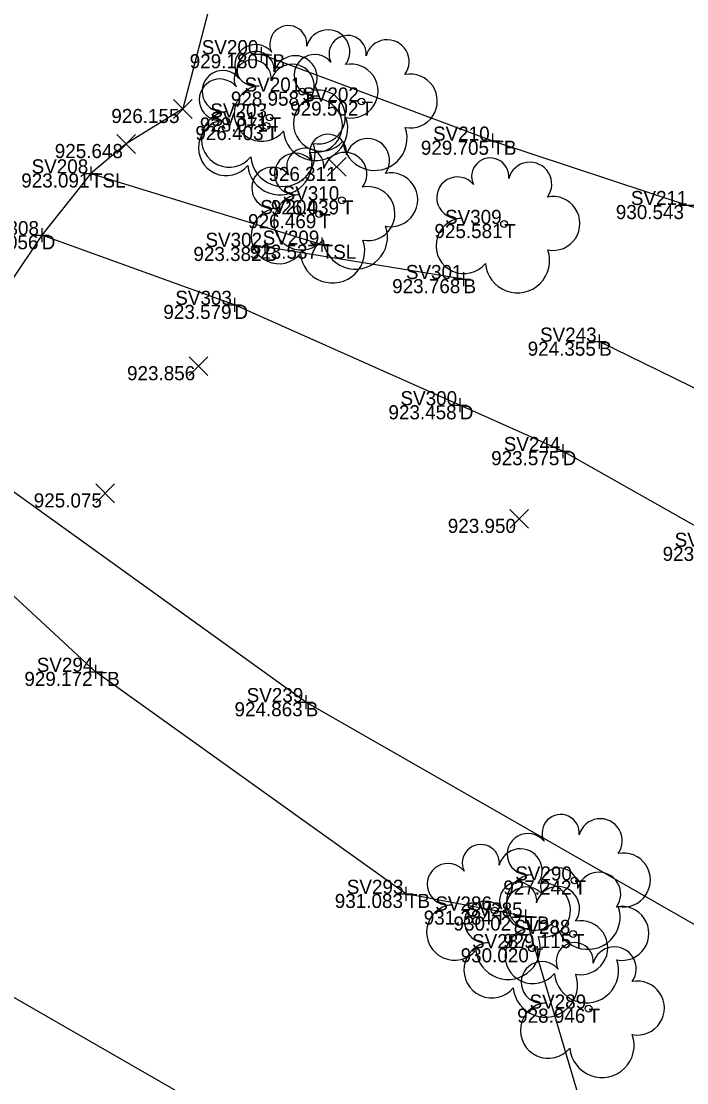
# Model space of a CAD drawing. Extents: x 1988835 to 1989144, y 657973 to 659339.
# Drawn here: x 1988889.6 to 1988936.8, y 658662.1 to 658737.4 of the extents above; entities that cross this region are included whole.
import ezdxf

# ---------------------------------------------------------------- set-up
doc = ezdxf.new("R2010")
doc.units = 0
for name, color, linetype in [('DR_X_Ditch', 7, 'Continuous'), ('DT_X_Terrain_Boundary', 7, 'Continuous'), ('SV_X_Break_Lines', 7, 'Continuous'), ('SV_X_Random_Point', 7, 'Continuous'), ('SV_X_Shot_Marker', 7, 'Continuous'), ('SV_X_Text_Comment', 7, 'Continuous'), ('SV_X_Toe_of_Slope', 7, 'Continuous'), ('SV_X_Top_of_Bank', 7, 'Continuous'), ('UT_X_Telecom', 7, 'Continuous'), ('UT_X_Telecom_Cells', 7, 'Continuous'), ('VG_X_Cells', 7, 'Continuous')]:
    doc.layers.add(name, color=color, linetype=linetype)

msp = doc.modelspace()

# ---------------------------------------------------------------- linework, layer by layer
at = {"layer": 'DR_X_Ditch'}
for points in [[(1988920.687, 658710.159), (1988904.704, 658717.281), (1988891.031, 658722.224)], [(1988954.33, 658694.137), (1988940.011, 658700.115), (1988927.983, 658706.906), (1988920.687, 658710.159)]]:
    msp.add_lwpolyline(points, dxfattribs=at)
at = {"layer": 'DT_X_Terrain_Boundary'}
msp.add_lwpolyline([(1988987.829, 658845.226), (1988984.806, 658799.592), (1988977.838, 658799.782), (1988968.827, 658798.912), (1988942.792, 658792.822), (1988927.355, 658779.107), (1988913.541, 658771.147), (1988908.127, 658758.455), (1988901.041, 658731.181), (1988897.019, 658728.695), (1988894.525, 658726.606), (1988891.031, 658722.224), (1988888.806, 658718.864), (1988886.026, 658711.785), (1988888.695, 658704.246), (1988881.579, 658703.527), (1988864.624, 658687.792), (1988839.989, 658661.752), (1988877.263, 658674.92), (1988925.042, 658647.449), (1988928.997, 658641.521), (1988939.918, 658638.356), (1988953.745, 658630.003), (1988967.235, 658593.527)], dxfattribs=at)
at = {"layer": 'SV_X_Break_Lines'}
for points in [[(1988920.949, 658719.109), (1988906.849, 658721.392)], [(1988961.012, 658699.789), (1988959.296, 658702.449), (1988957.403, 658701.554), (1988930.572, 658714.671)], [(1988950.438, 658683.541), (1988950.966, 658681.818), (1988947.272, 658678.12), (1988941.777, 658670.765), (1988909.757, 658689.092), (1988888.695, 658704.246)]]:
    msp.add_lwpolyline(points, dxfattribs=at)
at = {"layer": 'SV_X_Random_Point'}
for p, q in [((1988900.374, 658730.514), (1988901.708, 658731.849)), ((1988900.374, 658731.849), (1988901.708, 658730.514)), ((1988896.352, 658728.027), (1988897.685, 658729.362)), ((1988896.352, 658729.362), (1988897.685, 658728.027)), ((1988911.284, 658726.402), (1988912.618, 658727.737)), ((1988911.284, 658727.737), (1988912.618, 658726.402)), ((1988901.482, 658712.265), (1988902.815, 658713.6)), ((1988901.482, 658713.6), (1988902.815, 658712.265)), ((1988894.872, 658703.239), (1988896.206, 658704.574)), ((1988894.872, 658704.574), (1988896.206, 658703.239)), ((1988924.229, 658701.434), (1988925.563, 658702.769)), ((1988924.229, 658702.769), (1988925.563, 658701.434))]:
    msp.add_line(p, q, dxfattribs=at)
at = {"layer": 'SV_X_Shot_Marker'}
for p, q in [((1988906.592, 658735.565), (1988906.592, 658734.565)), ((1988906.092, 658735.065), (1988907.092, 658735.065)), ((1988906.592, 658735.065), (1988906.592, 658735.065)), ((1988922.496, 658728.928), (1988923.496, 658728.928)), ((1988922.996, 658729.428), (1988922.996, 658728.428)), ((1988922.996, 658728.928), (1988922.996, 658728.928)), ((1988894.025, 658726.606), (1988895.025, 658726.606)), ((1988894.525, 658727.106), (1988894.525, 658726.106)), ((1988894.525, 658726.606), (1988894.525, 658726.606)), ((1988936.302, 658724.364), (1988937.302, 658724.364)), ((1988891.031, 658722.724), (1988891.031, 658721.724)), ((1988890.531, 658722.224), (1988891.531, 658722.224)), ((1988891.031, 658722.224), (1988891.031, 658722.224)), ((1988910.893, 658722.052), (1988910.893, 658721.052)), ((1988906.349, 658721.392), (1988907.349, 658721.392)), ((1988906.849, 658721.892), (1988906.849, 658720.892)), ((1988906.849, 658721.392), (1988906.849, 658721.392)), ((1988910.393, 658721.552), (1988911.393, 658721.552)), ((1988910.893, 658721.552), (1988910.893, 658721.552)), ((1988920.449, 658719.109), (1988921.449, 658719.109)), ((1988920.949, 658719.609), (1988920.949, 658718.609)), ((1988920.949, 658719.109), (1988920.949, 658719.109)), ((1988904.704, 658717.781), (1988904.704, 658716.781)), ((1988904.204, 658717.281), (1988905.204, 658717.281)), ((1988904.704, 658717.281), (1988904.704, 658717.281)), ((1988930.572, 658715.171), (1988930.572, 658714.171)), ((1988930.072, 658714.671), (1988931.072, 658714.671)), ((1988930.572, 658714.671), (1988930.572, 658714.671)), ((1988920.687, 658710.659), (1988920.687, 658709.659)), ((1988920.187, 658710.159), (1988921.187, 658710.159)), ((1988920.687, 658710.159), (1988920.687, 658710.159)), ((1988927.483, 658706.906), (1988928.483, 658706.906)), ((1988927.983, 658707.406), (1988927.983, 658706.406)), ((1988927.983, 658706.906), (1988927.983, 658706.906)), ((1988894.359, 658691.243), (1988895.359, 658691.243)), ((1988894.859, 658691.743), (1988894.859, 658690.743)), ((1988894.859, 658691.243), (1988894.859, 658691.243)), ((1988909.757, 658689.592), (1988909.757, 658688.592)), ((1988909.257, 658689.092), (1988910.257, 658689.092)), ((1988909.757, 658689.092), (1988909.757, 658689.092)), ((1988916.868, 658675.991), (1988916.868, 658674.991)), ((1988916.368, 658675.491), (1988917.368, 658675.491)), ((1988916.868, 658675.491), (1988916.868, 658675.491)), ((1988924.845, 658673.887), (1988925.845, 658673.887)), ((1988925.345, 658674.387), (1988925.345, 658673.387)), ((1988925.345, 658673.887), (1988925.345, 658673.887))]:
    msp.add_line(p, q, dxfattribs=at)
at = {"layer": 'SV_X_Toe_of_Slope'}
msp.add_lwpolyline([(1988894.525, 658726.606), (1988910.893, 658721.552)], dxfattribs=at)
at = {"layer": 'SV_X_Top_of_Bank'}
for points in [[(1988906.592, 658735.065), (1988922.996, 658728.928), (1988936.802, 658724.364), (1988946.553, 658721.548), (1988963.916, 658715.502), (1988970.033, 658699.243), (1988969.072, 658687.698)], [(1988925.042, 658647.449), (1988930.237, 658657.354), (1988925.345, 658673.887), (1988916.868, 658675.491), (1988894.859, 658691.243), (1988881.579, 658703.527)]]:
    msp.add_lwpolyline(points, dxfattribs=at)
at = {"layer": 'VG_X_Cells'}
for centre in [(1988909.511, 658732.411), (1988913.715, 658731.708), (1988906.982, 658729.97), (1988907.191, 658730.574), (1988912.327, 658724.699), (1988910.713, 658723.719), (1988923.828, 658723.019), (1988928.827, 658676.442), (1988923.159, 658674.308), (1988928.72, 658672.646), (1988925.807, 658671.633), (1988929.821, 658667.35)]:
    msp.add_circle(centre, 0.24, dxfattribs=at)
for centre, radius, start, end in [((1988908.527, 658735.778), 1.317, 354.0047, 205.97412), ((1988911.337, 658735.24), 1.553, 323.82996, 165.0376), ((1988912.731, 658735.075), 1.317, 354.0047, 205.97412), ((1988906.201, 658734.275), 1.471, 39.06254, 279.54124), ((1988915.541, 658734.537), 1.553, 323.82996, 165.0376), ((1988906.207, 658733.941), 1.317, 354.0047, 205.97412), ((1988909.017, 658733.403), 1.553, 323.82996, 165.0376), ((1988910.406, 658733.572), 1.471, 39.06254, 279.54124), ((1988905.998, 658733.337), 1.317, 354.0047, 205.97412), ((1988908.808, 658732.799), 1.553, 323.82996, 165.0376), ((1988912.971, 658732.447), 1.915, 259.14531, 101.45961), ((1988903.672, 658731.834), 1.471, 39.06254, 279.54124), ((1988903.881, 658732.438), 1.471, 39.06254, 279.54124), ((1988917.175, 658731.744), 1.915, 259.14531, 101.45961), ((1988906.657, 658730.862), 1.974, 96.17219, 320.57371), ((1988910.651, 658730.61), 1.915, 259.14531, 101.45961), ((1988910.862, 658730.159), 1.974, 96.17219, 320.57371), ((1988910.442, 658730.006), 1.915, 259.14531, 101.45961), ((1988904.337, 658729.025), 1.974, 96.17219, 320.57371), ((1988904.128, 658728.421), 1.974, 96.17219, 320.57371), ((1988910.457, 658729.806), 2.284, 184.94757, 19.45715), ((1988914.661, 658729.103), 2.284, 184.94757, 19.45715), ((1988908.137, 658727.968), 2.284, 184.94757, 19.45715), ((1988911.343, 658728.066), 1.317, 354.0047, 205.97412), ((1988914.153, 658727.528), 1.553, 323.82996, 165.0376), ((1988907.928, 658727.364), 2.284, 184.94757, 19.45715), ((1988909.017, 658726.563), 1.471, 39.06254, 279.54124), ((1988909.729, 658727.087), 1.317, 354.0047, 205.97412), ((1988912.539, 658726.548), 1.553, 323.82996, 165.0376), ((1988922.844, 658726.387), 1.317, 354.0047, 205.97412), ((1988925.654, 658725.848), 1.553, 323.82996, 165.0376), ((1988907.404, 658725.583), 1.471, 39.06254, 279.54124), ((1988915.787, 658724.735), 1.915, 259.14531, 101.45961), ((1988914.173, 658723.755), 1.915, 259.14531, 101.45961), ((1988920.519, 658724.883), 1.471, 39.06254, 279.54124), ((1988909.473, 658723.15), 1.974, 96.17219, 320.57371), ((1988927.288, 658723.055), 1.915, 259.14531, 101.45961), ((1988907.86, 658722.171), 1.974, 96.17219, 320.57371), ((1988920.975, 658721.471), 1.974, 96.17219, 320.57371), ((1988913.273, 658722.094), 2.284, 184.94757, 19.45715), ((1988911.659, 658721.114), 2.284, 184.94757, 19.45715), ((1988924.774, 658720.414), 2.284, 184.94757, 19.45715), ((1988927.843, 658679.809), 1.317, 354.0047, 205.97412), ((1988930.653, 658679.271), 1.553, 323.82996, 165.0376), ((1988925.518, 658678.306), 1.471, 39.06254, 279.54124), ((1988922.175, 658677.676), 1.317, 354.0047, 205.97412), ((1988924.985, 658677.137), 1.553, 323.82996, 165.0376), ((1988932.287, 658676.478), 1.915, 259.14531, 101.45961), ((1988919.85, 658676.172), 1.471, 39.06254, 279.54124), ((1988925.974, 658674.893), 1.974, 96.17219, 320.57371), ((1988927.736, 658676.013), 1.317, 354.0047, 205.97412), ((1988930.546, 658675.475), 1.553, 323.82996, 165.0376), ((1988924.823, 658675.001), 1.317, 354.0047, 205.97412), ((1988925.411, 658674.51), 1.471, 39.06254, 279.54124), ((1988927.633, 658674.462), 1.553, 323.82996, 165.0376), ((1988926.619, 658674.344), 1.915, 259.14531, 101.45961), ((1988920.306, 658672.76), 1.974, 96.17219, 320.57371), ((1988922.497, 658673.497), 1.471, 39.06254, 279.54124), ((1988929.773, 658673.837), 2.284, 184.94757, 19.45715), ((1988932.18, 658672.682), 1.915, 259.14531, 101.45961), ((1988925.867, 658671.097), 1.974, 96.17219, 320.57371), ((1988929.267, 658671.669), 1.915, 259.14531, 101.45961), ((1988924.106, 658671.703), 2.284, 184.94757, 19.45715), ((1988922.953, 658670.084), 1.974, 96.17219, 320.57371), ((1988928.837, 658670.717), 1.317, 354.0047, 205.97412), ((1988931.647, 658670.179), 1.553, 323.82996, 165.0376), ((1988929.667, 658670.04), 2.284, 184.94757, 19.45715), ((1988926.511, 658669.214), 1.471, 39.06254, 279.54124), ((1988926.753, 658669.028), 2.284, 184.94757, 19.45715), ((1988933.281, 658667.386), 1.915, 259.14531, 101.45961), ((1988926.967, 658665.801), 1.974, 96.17219, 320.57371), ((1988930.767, 658664.745), 2.284, 184.94757, 19.45715)]:
    msp.add_arc(centre, radius, start, end, dxfattribs=at)

# ---------------------------------------------------------------- texts
at = {"layer": 'SV_X_Text_Comment'}
for s, p in [('SV200', (1988902.385, 658735.065)), ('SV201', (1988905.424, 658732.411)), ('SV202', (1988909.512, 658731.708)), ('SV203', (1988902.995, 658730.574)), ('SV311', (1988902.999, 658729.97)), ('SV210', (1988918.788, 658728.928)), ('SV208', (1988890.319, 658726.606)), ('SV310', (1988908.12, 658724.699)), ('SV211', (1988932.819, 658724.364)), ('SV204', (1988906.535, 658723.719)), ('SV309', (1988919.64, 658723.019)), ('SV308', (1988886.825, 658722.224)), ('SV302', (1988902.646, 658721.392)), ('SV209', (1988906.706, 658721.552)), ('SV301', (1988916.862, 658719.109)), ('SV303', (1988900.508, 658717.281)), ('SV243', (1988926.376, 658714.671)), ('SV300', (1988916.48, 658710.159)), ('SV244', (1988923.805, 658706.906)), ('SV241', (1988935.924, 658700.115)), ('SV294', (1988890.682, 658691.243)), ('SV239', (1988905.57, 658689.092)), ('SV290', (1988924.62, 658676.442)), ('SV293', (1988912.673, 658675.491)), ('SV286', (1988918.949, 658674.308)), ('SV285', (1988921.128, 658673.887)), ('SV288', (1988924.514, 658672.646)), ('SV287', (1988921.558, 658671.633)), ('SV289', (1988925.633, 658667.35))]:
    msp.add_text(s, height=1, dxfattribs=at).set_placement(p)
at = {"layer": 'UT_X_Telecom'}
for s, p in [('TB', (1988906.592, 658734.065)), ('T', (1988909.511, 658731.411)), ('T', (1988913.715, 658730.708)), ('T', (1988907.191, 658729.574)), ('T', (1988906.982, 658728.97)), ('TB', (1988922.996, 658727.928)), ('TSL', (1988894.525, 658725.606)), ('T', (1988912.327, 658723.699)), ('T', (1988910.713, 658722.719)), ('T', (1988923.828, 658722.019)), ('D', (1988891.031, 658721.224)), ('B', (1988906.849, 658720.392)), ('TSL', (1988910.893, 658720.552)), ('B', (1988920.949, 658718.109)), ('D', (1988904.704, 658716.281)), ('B', (1988930.572, 658713.671)), ('D', (1988920.687, 658709.159)), ('D', (1988927.983, 658705.906)), ('TB', (1988894.859, 658690.243)), ('B', (1988909.757, 658688.092)), ('T', (1988928.827, 658675.442)), ('TB', (1988916.868, 658674.491)), ('T', (1988923.159, 658673.308)), ('TB', (1988925.345, 658672.887)), ('T', (1988928.72, 658671.646)), ('T', (1988925.807, 658670.633)), ('T', (1988929.821, 658666.35))]:
    msp.add_text(s, height=1, dxfattribs=at).set_placement(p)
at = {"layer": 'UT_X_Telecom_Cells'}
for s, p in [('929.180', (1988901.531, 658734.065)), ('928.958', (1988904.451, 658731.411)), ('929.502', (1988908.659, 658730.708)), ('926.155', (1988895.97, 658730.181)), ('928.071', (1988902.25, 658729.574)), ('926.403', (1988901.932, 658728.97)), ('925.648', (1988891.959, 658727.695)), ('929.705', (1988917.925, 658727.928)), ('923.091', (1988889.584, 658725.606)), ('926.311', (1988907.114, 658726.069)), ('926.039', (1988907.286, 658723.699)), ('930.543', (1988931.752, 658723.364)), ('926.469', (1988905.672, 658722.719)), ('925.581', (1988918.887, 658722.019)), ('923.056', (1988885.967, 658721.224)), ('923.382', (1988901.793, 658720.392)), ('923.537', (1988905.79, 658720.552)), ('923.768', (1988915.89, 658718.109)), ('923.579', (1988899.663, 658716.281)), ('924.355', (1988925.501, 658713.671)), ('923.856', (1988897.085, 658711.932)), ('923.458', (1988915.627, 658709.159)), ('923.575', (1988922.912, 658705.906)), ('925.075', (1988890.468, 658702.907)), ('923.950', (1988919.835, 658701.101)), ('923.301', (1988935.07, 658699.115)), ('929.172', (1988889.803, 658690.243)), ('924.863', (1988904.708, 658688.092)), ('927.242', (1988923.771, 658675.442)), ('931.083', (1988911.819, 658674.491)), ('931.384', (1988918.128, 658673.308)), ('930.027', (1988920.242, 658672.887)), ('929.115', (1988923.753, 658671.646)), ('930.020', (1988920.746, 658670.633)), ('928.946', (1988924.757, 658666.35))]:
    msp.add_text(s, height=1, dxfattribs=at).set_placement(p)

doc.saveas('drawing.dxf')
